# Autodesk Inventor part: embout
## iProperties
Shininess: 64.0
Length Units: 11269
Angle Units: 11279
Time Units: 11290
Mass Units: 11283
Length Display Precision: 3
Angle Display Precision: 2
Compacted: True
Part Number: embout
Document SubType Name: Modeling
Created: 2004-12
Material: Par défaut
Designer: LEGERET Philippe
Density: 0.0
Volumn: 0.0
Area: 0.0
PropertySet Name: Model Information
Control State: 0
Master: False
Checked Out: False
Author: LEGERET Philippe
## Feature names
1. Extrusion1
2. Extrusion2
3. Extrusion3
4. Extrusion4
5. Extrusion5
6. Perçage1 [Hole]
7. Réseau circulaire1 [Circular Pattern]
8. Réseau circulaire2 [Circular Pattern]
9. Symétrie1 [Mirror]
